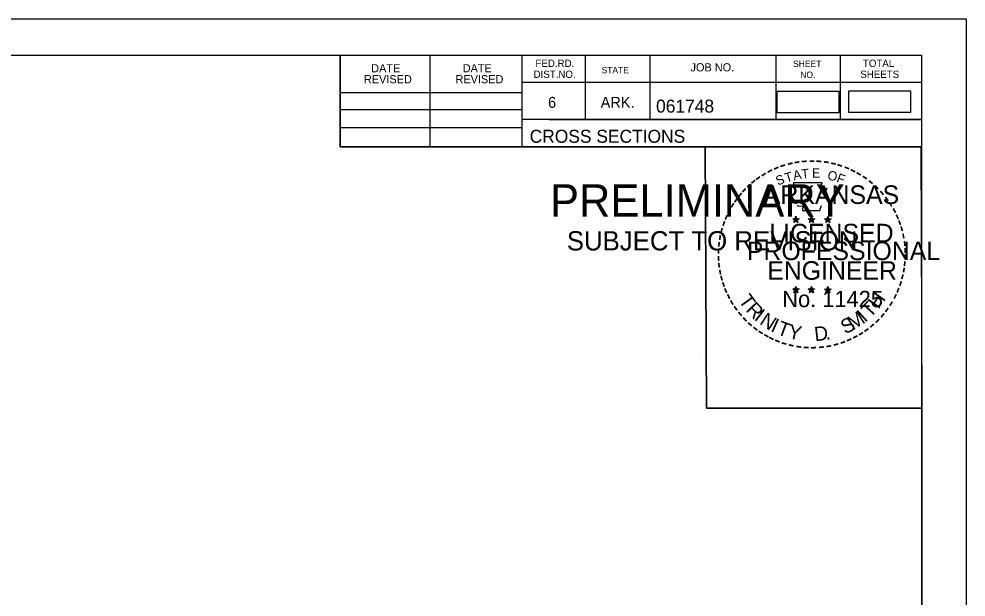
# Model space of a CAD drawing. Extents: x 961436 to 1372525, y 380079 to 2027791.
# Drawn here: x 1371255.8 to 1371357.8, y 380260.1 to 380322.4 of the extents above; entities that cross this region are included whole.
import ezdxf

# ---------------------------------------------------------------- set-up
doc = ezdxf.new("R2010")
doc.units = 0
for name, color, linetype in [('R_Alt Surface', 7, 'Continuous'), ('R_Border', 7, 'Continuous'), ('R_Border PE', 7, 'Continuous'), ('R_Border Prem', 7, 'Continuous'), ('R_No Plot', 7, 'Continuous')]:
    doc.layers.add(name, color=color, linetype=linetype)

msp = doc.modelspace()

# ---------------------------------------------------------------- linework, layer by layer
at = {"layer": 'R_Alt Surface'}
for points in [[(1371337.44, 380312.35), (1371344.15, 380312.35), (1371344.15, 380314.59), (1371337.44, 380314.59)], [(1371345.16, 380312.38), (1371351.87, 380312.38), (1371351.87, 380314.62), (1371345.16, 380314.62)]]:
    msp.add_lwpolyline(points, close=True, dxfattribs=at)
at = {"layer": 'R_Border'}
for p, q in [((1371036.88, 380318.52), (1371353.06, 380318.52)), ((1371290.42, 380308.64), (1371290.42, 380318.52)), ((1371300.1, 380308.64), (1371300.1, 380318.52)), ((1371309.96, 380318.52), (1371309.96, 380308.64)), ((1371316.8, 380318.52), (1371316.8, 380311.58)), ((1371323.74, 380318.52), (1371323.74, 380311.58)), ((1371337.32, 380318.52), (1371337.32, 380311.58)), ((1371344.26, 380318.52), (1371344.26, 380311.58)), ((1371353.06, 380113.06), (1371353.06, 380318.52)), ((1371353.06, 380315.58), (1371309.96, 380315.58)), ((1371353.06, 380315.6), (1371353.06, 380315.6)), ((1371290.42, 380314.5), (1371309.96, 380314.5)), ((1371290.42, 380312.64), (1371309.96, 380312.64)), ((1371353.06, 380311.58), (1371309.96, 380311.58)), ((1371312.92, 380311.58), (1371353.06, 380311.58)), ((1371290.42, 380310.7), (1371309.96, 380310.7)), ((1371353.06, 380308.64), (1371290.42, 380308.64))]:
    msp.add_line(p, q, dxfattribs=at)
at = {"layer": 'R_Border PE'}
for p, q in [((1371339.14, 380300.89), (1371339.49, 380300.78)), ((1371339.14, 380300.89), (1371339.39, 380300.85)), ((1371339.14, 380300.89), (1371339.38, 380300.77)), ((1371339.27, 380300.49), (1371339.49, 380300.78)), ((1371339.27, 380300.49), (1371339.4, 380300.73)), ((1371339.27, 380300.49), (1371339.49, 380300.7)), ((1371339.49, 380301.15), (1371339.45, 380300.9)), ((1371339.49, 380300.78), (1371339.49, 380301.15)), ((1371339.49, 380301.15), (1371339.54, 380300.9)), ((1371339.84, 380300.89), (1371339.49, 380300.78)), ((1371339.7, 380300.49), (1371339.49, 380300.78)), ((1371339.7, 380300.49), (1371339.49, 380300.7)), ((1371339.84, 380300.89), (1371339.55, 380300.85)), ((1371339.7, 380300.49), (1371339.57, 380300.78)), ((1371339.84, 380300.89), (1371339.63, 380300.79)), ((1371340.81, 380300.89), (1371341.16, 380300.78)), ((1371340.81, 380300.89), (1371341.06, 380300.85)), ((1371340.81, 380300.89), (1371341.05, 380300.77)), ((1371340.94, 380300.49), (1371341.16, 380300.78)), ((1371340.94, 380300.49), (1371341.07, 380300.73)), ((1371340.94, 380300.49), (1371341.16, 380300.7)), ((1371341.16, 380301.15), (1371341.12, 380300.9)), ((1371341.16, 380300.78), (1371341.16, 380301.15)), ((1371341.16, 380301.15), (1371341.21, 380300.9)), ((1371341.51, 380300.89), (1371341.16, 380300.78)), ((1371341.37, 380300.49), (1371341.16, 380300.78)), ((1371341.37, 380300.49), (1371341.16, 380300.7)), ((1371341.51, 380300.89), (1371341.22, 380300.85)), ((1371341.37, 380300.49), (1371341.24, 380300.78)), ((1371341.51, 380300.89), (1371341.3, 380300.79)), ((1371342.58, 380300.88), (1371342.92, 380300.77)), ((1371342.58, 380300.88), (1371342.83, 380300.84)), ((1371342.58, 380300.88), (1371342.81, 380300.76)), ((1371342.71, 380300.47), (1371342.92, 380300.77)), ((1371342.71, 380300.47), (1371342.83, 380300.72)), ((1371342.71, 380300.47), (1371342.92, 380300.69)), ((1371342.92, 380301.14), (1371342.88, 380300.88)), ((1371342.92, 380300.77), (1371342.92, 380301.14)), ((1371342.92, 380301.14), (1371342.97, 380300.89)), ((1371343.27, 380300.88), (1371342.92, 380300.77)), ((1371343.14, 380300.47), (1371342.92, 380300.77)), ((1371343.14, 380300.47), (1371342.92, 380300.69)), ((1371343.27, 380300.88), (1371342.99, 380300.83)), ((1371343.14, 380300.47), (1371343, 380300.77)), ((1371343.27, 380300.88), (1371343.07, 380300.78)), ((1371339.49, 380293.58), (1371339.45, 380293.32)), ((1371339.49, 380293.21), (1371339.49, 380293.58)), ((1371339.49, 380293.58), (1371339.54, 380293.33)), ((1371341.16, 380293.58), (1371341.11, 380293.32)), ((1371341.16, 380293.21), (1371341.16, 380293.58)), ((1371341.16, 380293.58), (1371341.2, 380293.33)), ((1371342.92, 380293.57), (1371342.88, 380293.31)), ((1371342.92, 380293.2), (1371342.92, 380293.57)), ((1371342.92, 380293.57), (1371342.97, 380293.32)), ((1371339.14, 380293.32), (1371339.49, 380293.21)), ((1371339.14, 380293.32), (1371339.39, 380293.28)), ((1371339.14, 380293.32), (1371339.37, 380293.2)), ((1371339.27, 380292.91), (1371339.49, 380293.21)), ((1371339.27, 380292.91), (1371339.4, 380293.16)), ((1371339.27, 380292.91), (1371339.48, 380293.13)), ((1371339.7, 380292.91), (1371339.48, 380293.13)), ((1371339.83, 380293.32), (1371339.49, 380293.21)), ((1371339.7, 380292.91), (1371339.49, 380293.21)), ((1371339.83, 380293.32), (1371339.55, 380293.27)), ((1371339.7, 380292.91), (1371339.56, 380293.2)), ((1371339.83, 380293.32), (1371339.63, 380293.22)), ((1371340.81, 380293.32), (1371341.16, 380293.21)), ((1371340.81, 380293.32), (1371341.06, 380293.28)), ((1371340.81, 380293.32), (1371341.04, 380293.2)), ((1371340.94, 380292.91), (1371341.16, 380293.21)), ((1371340.94, 380292.91), (1371341.07, 380293.16)), ((1371340.94, 380292.91), (1371341.15, 380293.13)), ((1371341.37, 380292.91), (1371341.15, 380293.13)), ((1371341.5, 380293.32), (1371341.16, 380293.21)), ((1371341.37, 380292.91), (1371341.16, 380293.21)), ((1371341.5, 380293.32), (1371341.22, 380293.27)), ((1371341.37, 380292.91), (1371341.23, 380293.2)), ((1371341.5, 380293.32), (1371341.3, 380293.22)), ((1371342.57, 380293.31), (1371342.92, 380293.2)), ((1371342.57, 380293.31), (1371342.83, 380293.27)), ((1371342.57, 380293.31), (1371342.81, 380293.19)), ((1371342.71, 380292.9), (1371342.92, 380293.2)), ((1371342.71, 380292.9), (1371342.83, 380293.15)), ((1371342.71, 380292.9), (1371342.92, 380293.12)), ((1371343.27, 380293.31), (1371342.92, 380293.2)), ((1371343.14, 380292.9), (1371342.92, 380293.2)), ((1371343.14, 380292.9), (1371342.92, 380293.12)), ((1371343.27, 380293.31), (1371342.98, 380293.26)), ((1371343.14, 380292.9), (1371343, 380293.19)), ((1371343.27, 380293.31), (1371343.07, 380293.21))]:
    msp.add_line(p, q, dxfattribs=at)
for points in [[(1371339.18, 380304.77), (1371339.45, 380303.95)], [(1371342.69, 380303.85), (1371342.84, 380304.13), (1371342.15, 380304.11), (1371342.3, 380304.77), (1371339.18, 380304.77)], [(1371339.67, 380302.35), (1371339.67, 380302.26), (1371340.24, 380302.24), (1371340.18, 380301.77), (1371342.05, 380301.77), (1371342.25, 380302.31)], [(1371339.49, 380301.15), (1371339.7, 380300.49), (1371339.14, 380300.89), (1371339.84, 380300.89), (1371339.27, 380300.49), (1371339.49, 380301.15)], [(1371341.16, 380301.15), (1371341.37, 380300.49), (1371340.81, 380300.89), (1371341.51, 380300.89), (1371340.94, 380300.49), (1371341.16, 380301.15)], [(1371342.92, 380301.14), (1371343.14, 380300.47), (1371342.58, 380300.88), (1371343.27, 380300.88), (1371342.71, 380300.47), (1371342.92, 380301.14)], [(1371339.49, 380293.58), (1371339.7, 380292.91), (1371339.14, 380293.32), (1371339.83, 380293.32), (1371339.27, 380292.91), (1371339.49, 380293.58)], [(1371341.16, 380293.58), (1371341.37, 380292.91), (1371340.81, 380293.32), (1371341.5, 380293.32), (1371340.94, 380292.91), (1371341.16, 380293.58)], [(1371342.92, 380293.57), (1371343.14, 380292.9), (1371342.57, 380293.31), (1371343.27, 380293.31), (1371342.71, 380292.9), (1371342.92, 380293.57)]]:
    msp.add_lwpolyline(points, dxfattribs=at)
for centre, radius in [((1371339.49, 380300.78), 0.172), ((1371339.49, 380300.78), 0.145), ((1371339.49, 380300.78), 0.116), ((1371339.49, 380300.78), 0.0991), ((1371339.49, 380300.78), 0.0747), ((1371339.49, 380300.78), 0.0495), ((1371339.49, 380300.78), 0.0296), ((1371341.16, 380300.78), 0.172), ((1371341.16, 380300.78), 0.145), ((1371341.16, 380300.78), 0.116), ((1371341.16, 380300.78), 0.0991), ((1371341.16, 380300.78), 0.0747), ((1371341.16, 380300.78), 0.0495), ((1371341.16, 380300.78), 0.0296), ((1371342.92, 380300.77), 0.172), ((1371342.92, 380300.77), 0.145), ((1371342.92, 380300.77), 0.116), ((1371342.92, 380300.77), 0.0991), ((1371342.92, 380300.77), 0.0747), ((1371342.92, 380300.77), 0.0495), ((1371342.92, 380300.77), 0.0296), ((1371339.49, 380293.21), 0.172), ((1371339.49, 380293.21), 0.145), ((1371339.49, 380293.21), 0.116), ((1371339.49, 380293.21), 0.0991), ((1371339.49, 380293.21), 0.0747), ((1371339.49, 380293.21), 0.0495), ((1371339.49, 380293.21), 0.0296), ((1371341.15, 380293.21), 0.172), ((1371341.15, 380293.21), 0.145), ((1371341.15, 380293.21), 0.116), ((1371341.15, 380293.21), 0.0991), ((1371341.15, 380293.21), 0.0747), ((1371341.15, 380293.21), 0.0495), ((1371341.15, 380293.21), 0.0296), ((1371342.92, 380293.2), 0.172), ((1371342.92, 380293.2), 0.145), ((1371342.92, 380293.2), 0.116), ((1371342.92, 380293.2), 0.0991), ((1371342.92, 380293.2), 0.0747), ((1371342.92, 380293.2), 0.0495), ((1371342.92, 380293.2), 0.0296)]:
    msp.add_circle(centre, radius, dxfattribs=at)
at = {"layer": 'R_No Plot'}
for p, q in [((1371024.48, 380322.41), (1371357.81, 380322.41)), ((1371329.09, 380286.18), (1371329.09, 380286.18))]:
    msp.add_line(p, q, dxfattribs=at)
for points in [[(1371024.47, 380322.41), (1371357.81, 380322.41), (1371357.81, 380109.08), (1371024.47, 380109.08)], [(1371270.8, 380318.52), (1371290.42, 380318.52), (1371290.42, 380308.64), (1371306.53, 380308.64), (1371329.73, 380308.64), (1371329.85, 380280.48), (1371353.06, 380280.48), (1371353.06, 380113.06), (1371036.88, 380113.06), (1371036.88, 380318.52)], [(1371329.73, 380308.64), (1371352.94, 380308.64), (1371353.06, 380280.48), (1371329.85, 380280.48)]]:
    msp.add_lwpolyline(points, close=True, dxfattribs=at)

# ---------------------------------------------------------------- texts
at = {"layer": 'R_Border'}
for s, height, p in [('FED.RD.', 0.782, (1371311.44, 380317.24)), ('SHEET', 0.684, (1371339.18, 380317.24)), ('TOTAL', 0.782, (1371346.7, 380317.24)), ('DATE', 0.879, (1371293.75, 380316.66)), ('DATE', 0.879, (1371303.61, 380316.66)), ('STATE', 0.684, (1371318.56, 380316.56)), ('JOB NO.', 0.879, (1371328.14, 380316.76)), ('REVISED', 0.879, (1371292.97, 380315.48)), ('REVISED', 0.879, (1371302.83, 380315.48)), ('DIST.NO.', 0.782, (1371311.24, 380316.06)), ('NO.', 0.684, (1371339.96, 380316.06)), ('SHEETS', 0.782, (1371346.42, 380316.06)), ('6', 1.17, (1371312.8, 380312.84)), ('ARK.', 1.172, (1371318.46, 380312.84)), ('061748', 1.4, (1371324.43, 380312.32)), ('CROSS SECTIONS', 1.4, (1371310.82, 380309.07))]:
    msp.add_text(s, height=height, rotation=360, dxfattribs=at).set_placement(p)
at = {"layer": 'R_Border PE'}
for s, height, rotation, p in [('-', 1.6, 19.1761, (1371337.93, 380305.9)), ('-', 1.6, 13.6301, (1371338.68, 380306.14)), ('-', 1.6, 10.2193, (1371339.36, 380306.3)), ('-', 1.6, 5.8968, (1371340.09, 380306.41)), ('-', 1.6, 0.1862, (1371340.86, 380306.48)), ('-', 1.6, 357.743, (1371341.58, 380306.47)), ('-', 1.6, 352.1617, (1371342.33, 380306.42)), ('-', 1.6, 347.2049, (1371343.05, 380306.3)), ('-', 1.6, 342.3362, (1371343.68, 380306.15)), ('-', 1.6, 34.0636, (1371336.07, 380304.94)), ('-', 1.6, 28.7918, (1371336.66, 380305.31)), ('-', 1.6, 24.3072, (1371337.3, 380305.63)), ('T', 1, 16.4036, (1371338.45, 380304.78)), ('A', 1, 11.2132, (1371339.28, 380305.03)), ('T', 1, 6.0228, (1371340.13, 380305.2)), ('E', 1, 0.8323, (1371341.23, 380305.31)), ('O', 1, 350.4515, (1371342.84, 380305.1)), ('F', 1, 340.0707, (1371343.79, 380304.87)), ('-', 1.6, 337.8551, (1371344.42, 380305.92)), ('-', 1.6, 334.1211, (1371345.05, 380305.65)), ('-', 1.6, 329.6409, (1371345.63, 380305.37)), ('-', 1.6, 42.9622, (1371334.58, 380303.75)), ('-', 1.6, 38.9507, (1371335.01, 380304.17)), ('-', 1.6, 36.2317, (1371335.49, 380304.55)), ('S', 1, 21.594, (1371337.54, 380304.45)), ('-', 1.6, 325.8627, (1371346.27, 380305.01)), ('-', 1.6, 320.5297, (1371346.88, 380304.58)), ('-', 1.6, 50.6142, (1371333.73, 380302.79)), ('-', 1.6, 48.423, (1371334.13, 380303.28)), ('ARKANSAS', 2, 360, (1371336.04, 380302.48)), ('-', 1.6, 315.5786, (1371347.48, 380304.09)), ('-', 1.6, 309.8797, (1371348.05, 380303.54)), ('-', 1.6, 54.2325, (1371333.32, 380302.22)), ('-', 1.6, 306.6522, (1371348.57, 380302.94)), ('-', 1.4, 303.6753, (1371349.06, 380302.37)), ('-', 1.6, 62.8713, (1371332.68, 380301.08)), ('-', 1.6, 58.0706, (1371332.99, 380301.7)), ('-', 1.6, 299.6684, (1371349.38, 380301.77)), ('-', 1.6, 72.3945, (1371332.2, 380299.84)), ('-', 1.6, 67.7743, (1371332.42, 380300.47)), ('DWB', 0.01, 360, (1371339.48, 380300.78)), ('DWB', 0.01, 360, (1371341.15, 380300.78)), ('DWB', 0.01, 360, (1371342.91, 380300.77)), ('-', 1.6, 294.6628, (1371349.7, 380301.16)), ('-', 1.6, 290.5728, (1371349.96, 380300.58)), ('-', 1.6, 75.461, (1371332, 380299.13)), ('LICENSED', 2, 360, (1371336.63, 380298.34)), ('-', 1.6, 285.1233, (1371350.19, 380300)), ('-', 1.6, 81.2013, (1371331.87, 380298.41)), ('-', 1.6, 280.5493, (1371350.39, 380299.26)), ('-', 1.6, 89.0622, (1371331.77, 380297.02)), ('-', 1.6, 85.1863, (1371331.79, 380297.72)), ('PROFESSIONAL', 2, 360, (1371334.21, 380296.43)), ('-', 1.6, 276.5962, (1371350.55, 380298.49)), ('-', 1.6, 274.3301, (1371350.61, 380297.77)), ('-', 1.6, 94.1959, (1371331.8, 380296.3)), ('-', 1.6, 269.9407, (1371350.65, 380297.13)), ('-', 1.6, 98.9479, (1371331.88, 380295.63)), ('ENGINEER', 2, 360, (1371336.4, 380294.31)), ('-', 1.6, 260.9953, (1371350.56, 380295.81)), ('-', 1.6, 263.5172, (1371350.63, 380296.47)), ('-', 1.6, 101.7149, (1371332.01, 380294.9)), ('-', 1.6, 105.4578, (1371332.17, 380294.3)), ('-', 1.6, 255.7626, (1371350.45, 380295.14)), ('-', 1.6, 109.0874, (1371332.39, 380293.67)), ('-', 1.6, 247.8887, (1371350.04, 380293.74)), ('-', 1.6, 252.8681, (1371350.27, 380294.42)), ('-', 1.6, 114.0643, (1371332.64, 380293.07)), ('-', 1.6, 115.7289, (1371332.95, 380292.46)), ('T', 1.54, 306.0406, (1371333.25, 380292.05)), ('No. 11425', 1.757, 360, (1371338.02, 380291.36)), ('DWB', 0.01, 360, (1371339.47, 380293.21)), ('DWB', 0.01, 360, (1371341.14, 380293.21)), ('DWB', 0.01, 360, (1371342.91, 380293.2)), ('H', 1.54, 54.6088, (1371348.37, 380291.08)), ('-', 1.6, 244.6197, (1371349.78, 380293.11)), ('-', 1.6, 120.4471, (1371333.3, 380291.87)), ('-', 1.6, 125.8934, (1371333.71, 380291.31)), ('R', 1.54, 314.005, (1371334.01, 380291)), ('T', 1.54, 46.6444, (1371347.48, 380290.14)), ('-', 1.6, 239.0712, (1371349.39, 380292.36)), ('-', 1.6, 130.7181, (1371334.17, 380290.76)), ('I', 1.54, 321.9694, (1371334.91, 380290.07)), ('N', 1.54, 326.5002, (1371335.48, 380289.6)), ('M', 1.54, 32.6563, (1371345.63, 380288.82)), ('I', 1.54, 42.1136, (1371346.92, 380289.66)), ('-', 1.6, 231.2538, (1371348.56, 380291.14)), ('-', 1.6, 233.8452, (1371348.99, 380291.71)), ('-', 1.6, 134.2238, (1371334.69, 380290.21)), ('-', 1.6, 138.9338, (1371335.21, 380289.75)), ('I', 1.54, 335.3603, (1371336.68, 380288.81)), ('T', 1.54, 339.8912, (1371337.35, 380288.48)), ('Y', 1.54, 347.8556, (1371338.56, 380288.04)), ('S', 1.54, 26.9312, (1371344.79, 380288.41)), ('-', 1.6, 221.0851, (1371347.55, 380290.07)), ('-', 1.6, 225.7653, (1371348.08, 380290.58)), ('-', 1.6, 144.6463, (1371335.77, 380289.34)), ('-', 1.6, 148.0898, (1371336.33, 380288.97)), ('-', 1.6, 151.5704, (1371336.91, 380288.65)), ('D', 1.54, 6.3969, (1371341.55, 380287.68)), ('-', 1.6, 212.2491, (1371346.47, 380289.21)), ('-', 1.6, 215.7363, (1371347.01, 380289.6)), ('-', 1.6, 154.6002, (1371337.43, 380288.4)), ('-', 1.6, 158.5612, (1371338.05, 380288.15)), ('-', 1.6, 162.7983, (1371338.74, 380287.93)), ('-', 1.6, 167.5555, (1371339.46, 380287.77)), ('.', 1.54, 13.7642, (1371342.74, 380287.81)), ('-', 1.6, 195.4743, (1371343.99, 380288.03)), ('-', 1.6, 200.7184, (1371344.67, 380288.27)), ('-', 1.6, 204.2516, (1371345.29, 380288.55)), ('-', 1.6, 207.3568, (1371345.91, 380288.87)), ('-', 1.6, 173.1155, (1371340.23, 380287.66)), ('-', 1.6, 176.5183, (1371340.98, 380287.61)), ('-', 1.6, 181.5918, (1371341.72, 380287.62)), ('-', 1.6, 185.8167, (1371342.53, 380287.7)), ('-', 1.6, 191.2858, (1371343.26, 380287.83))]:
    msp.add_text(s, height=height, rotation=rotation, dxfattribs=at).set_placement(p)
at = {"layer": 'R_Border Prem'}
for s, height, p in [('PRELIMINARY', 3.5, (1371313.01, 380301.1)), ('DWB', 0.01, (1371313.75, 380302.95)), ('SUBJECT TO REVISION', 2.0751, (1371314.82, 380297.47))]:
    msp.add_text(s, height=height, rotation=360, dxfattribs=at).set_placement(p)

doc.saveas('drawing.dxf')
